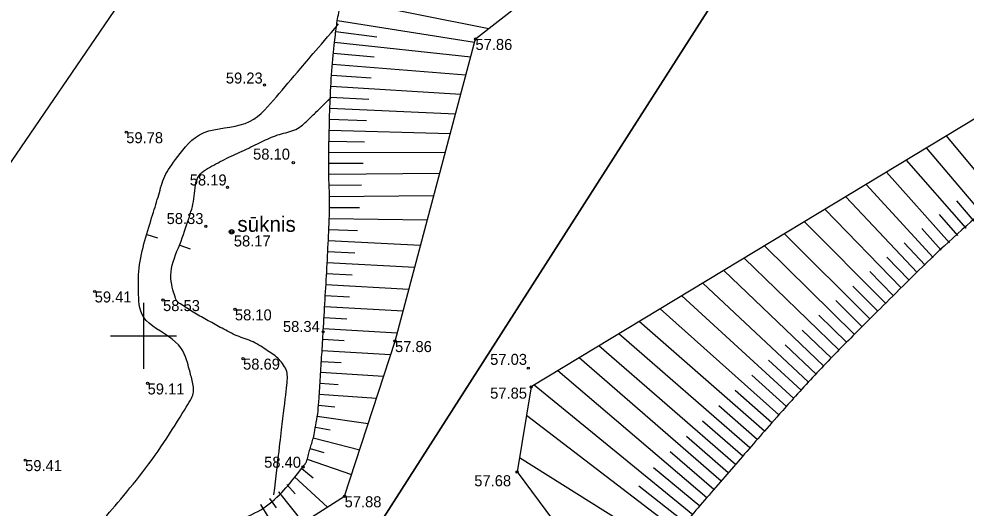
# Model space of a CAD drawing. Extents: x 616607 to 617499, y 408385 to 409695.
# Drawn here: x 616694.34 to 616737.38, y 408492.18 to 408514.38 of the extents above; entities that cross this region are included whole.
import ezdxf

# ---------------------------------------------------------------- set-up
doc = ezdxf.new("R2010")
doc.units = 0
for name, color, linetype in [('GEOD_ELEM_####_####_#', 7, 'Continuous'), ('HIDG_GRAV_####_####_#', 7, 'Continuous'), ('RAMI_UZMR_####_####_#', 7, 'Continuous'), ('RELJ_AATZ_####_TKST_#', 7, 'Continuous'), ('RELJ_ELEM_####_####_#', 7, 'Continuous'), ('RELJ_HORZ_PAMT_####_#', 7, 'Continuous'), ('RELJ_NOGA_####_####_#', 7, 'Continuous'), ('ROBZ_IERR_####_####_#', 7, 'Continuous'), ('ROBZ_UZMR_####_####_#', 7, 'Continuous'), ('UDTK_ELEM_####_####_#', 7, 'Continuous')]:
    doc.layers.add(name, color=color, linetype=linetype)

# ---------------------------------------------------------------- blocks, each defined once
blk = doc.blocks.new('PKT')
at = {"layer": 'RELJ_ELEM_####_####_#'}
blk.add_circle((0, 0), 0.05, dxfattribs=at)
blk = doc.blocks.new('UDSUKN')
at = {"layer": 'UDTK_ELEM_####_####_#'}
blk.add_circle((0, 0), 0.106, dxfattribs=at)
blk.add_text(' sūknis', height=0.7, dxfattribs=at).set_placement((0, 0))
blk = doc.blocks.new('KRUSTS')
at = {"layer": 'GEOD_ELEM_####_####_#'}
for p, q in [((0, 1.5), (0, 0)), ((-1.5, 0), (0, 0)), ((0, 0), (0, -1.5)), ((0, 0), (1.5, 0))]:
    blk.add_line(p, q, dxfattribs=at)

msp = doc.modelspace()

# ---------------------------------------------------------------- linework, layer by layer
at = {"layer": 'HIDG_GRAV_####_####_#'}
msp.add_lwpolyline([(616765.45, 408526.57), (616717.618, 408497.675), (616716.98, 408493.818), (616722.239, 408486.737), (616723.371, 408480.51), (616720.037, 408475.133), (616696.755, 408470.663), (616689.283, 408471.969), (616682.791, 408476.247), (616681.206, 408477.551), (616679.98, 408480.284), (616680.025, 408480.874), (616680.52, 408481.458), (616702.717, 408488.625), (616709.142, 408492.712), (616711.432, 408499.757), (616715.088, 408513.471), (616726.56, 408522.413), (616768.796, 408535.775)], dxfattribs=at)
at = {"layer": 'RAMI_UZMR_####_####_#'}
msp.add_lwpolyline([(617191.828, 409115.62), (617145.545, 408952.8), (617072.809, 408766.141), (616965.332, 408652.076), (616939.432, 408594.661), (616924.839, 408592.467), (616706.433, 408526.081), (616666.426, 408467.691)], dxfattribs=at)
at = {"layer": 'RELJ_HORZ_PAMT_####_#'}
for p, q in [((616700.159, 408504.591), (616700.635, 408504.438)), ((616701.653, 408504.116), (616702.121, 408503.939))]:
    msp.add_line(p, q, dxfattribs=at)
for points in [[(616696.187, 408489.283), (616697.051, 408490.308), (616697.915, 408491.333), (616698.779, 408492.358), (616699.992, 408493.796), (616701.077, 408495.342), (616702.062, 408496.949), (616702.342, 408497.407), (616702.195, 408498.072), (616702.062, 408498.557), (616701.728, 408499.776), (616699.817, 408500.621), (616699.782, 408501.889), (616699.75, 408503.051), (616700.055, 408504.338), (616700.432, 408505.53), (616700.706, 408506.398), (616700.914, 408507.26), (616701.474, 408508.013), (616702.562, 408509.474), (616704.808, 408509.403), (616705.94, 408510.727), (616706.917, 408511.87), (616707.893, 408513.013), (616708.87, 408514.156)], [(616705.931, 408492.781), (616706.128, 408494.455), (616706.325, 408496.129), (616706.523, 408497.803), (616706.59, 408498.372), (616706.179, 408498.964), (616705.677, 408499.298), (616704.989, 408499.757), (616704.251, 408499.964), (616703.564, 408500.342), (616702.947, 408500.681), (616702.34, 408501.017), (616701.736, 408501.406), (616701.613, 408501.486), (616701.488, 408501.594), (616701.447, 408501.728), (616701.099, 408502.866), (616701.684, 408504.165), (616702.068, 408505.34), (616702.338, 408506.163), (616702.335, 408507.276), (616703.097, 408507.689), (616703.887, 408508.117), (616704.687, 408508.469), (616705.485, 408508.853), (616706.157, 408509.175), (616706.968, 408509.296), (616707.502, 408509.815), (616707.84, 408510.144), (616708.178, 408510.473), (616708.516, 408510.803)]]:
    msp.add_open_spline(points, degree=3, dxfattribs=at)
at = {"layer": 'RELJ_NOGA_####_####_#'}
for p, q in [((616709.002, 408515.293), (616715.689, 408513.939)), ((616708.821, 408514.31), (616715.048, 408513.322)), ((616708.821, 408514.31), (616708.822, 408514.31)), ((616708.748, 408513.815), (616710.61, 408513.563)), ((616708.748, 408513.815), (616708.748, 408513.815)), ((616708.689, 408513.319), (616714.874, 408512.667)), ((616708.689, 408513.319), (616708.69, 408513.319)), ((616708.641, 408512.821), (616710.48, 408512.657)), ((616708.641, 408512.821), (616708.641, 408512.821)), ((616708.599, 408512.323), (616714.652, 408511.836)), ((616708.599, 408512.323), (616708.6, 408512.323)), ((616708.562, 408511.824), (616710.355, 408511.7)), ((616708.562, 408511.824), (616708.563, 408511.824)), ((616708.53, 408511.325), (616714.421, 408510.967)), ((616708.53, 408511.325), (616708.531, 408511.325)), ((616708.503, 408510.826), (616710.244, 408510.74)), ((616708.503, 408510.826), (616708.503, 408510.826)), ((616708.48, 408510.327), (616714.184, 408510.079)), ((616708.48, 408510.327), (616708.481, 408510.327)), ((616708.461, 408509.827), (616710.143, 408509.77)), ((616708.461, 408509.827), (616708.461, 408509.827)), ((616708.446, 408509.327), (616713.943, 408509.177)), ((616708.446, 408509.327), (616708.447, 408509.327)), ((616708.434, 408508.827), (616710.051, 408508.797)), ((616708.434, 408508.827), (616708.434, 408508.827)), ((616738.898, 408506.176), (616736.485, 408509.072)), ((616738.133, 408505.531), (616735.577, 408508.524)), ((616708.428, 408508.327), (616713.714, 408508.315)), ((616708.428, 408508.327), (616708.429, 408508.327)), ((616737.376, 408504.878), (616734.667, 408507.974)), ((616708.429, 408507.827), (616709.978, 408507.839)), ((616708.429, 408507.827), (616708.429, 408507.827)), ((616708.434, 408507.327), (616713.465, 408507.382)), ((616708.434, 408507.327), (616708.435, 408507.327)), ((616736.627, 408504.216), (616733.759, 408507.426)), ((616708.439, 408506.827), (616709.907, 408506.844)), ((616708.439, 408506.827), (616708.44, 408506.827)), ((616735.885, 408503.545), (616732.834, 408506.867)), ((616708.444, 408506.327), (616713.193, 408506.362)), ((616708.444, 408506.327), (616708.445, 408506.327)), ((616735.153, 408502.864), (616731.913, 408506.311)), ((616708.445, 408505.827), (616709.825, 408505.82)), ((616708.445, 408505.827), (616708.446, 408505.827)), ((616737.754, 408505.206), (616736.966, 408506.12)), ((616734.43, 408502.173), (616730.967, 408505.739)), ((616737, 408504.548), (616736.166, 408505.495)), ((616708.44, 408505.328), (616712.897, 408505.253)), ((616708.44, 408505.328), (616708.441, 408505.328)), ((616733.717, 408501.472), (616730.031, 408505.174)), ((616708.427, 408504.828), (616709.722, 408504.782)), ((616708.427, 408504.828), (616708.427, 408504.828)), ((616733.01, 408500.765), (616729.133, 408504.631)), ((616736.255, 408503.882), (616735.369, 408504.862)), ((616737, 408504.548), (616737, 408504.549)), ((616737.376, 408504.878), (616737.375, 408504.879)), ((616708.403, 408504.328), (616712.593, 408504.112)), ((616708.403, 408504.328), (616708.404, 408504.328)), ((616732.306, 408500.055), (616728.22, 408504.079)), ((616735.518, 408503.206), (616734.573, 408504.219)), ((616736.627, 408504.216), (616736.626, 408504.217)), ((616708.377, 408503.829), (616709.601, 408503.762)), ((616708.377, 408503.829), (616708.377, 408503.829)), ((616736.255, 408503.882), (616736.255, 408503.882)), ((616708.35, 408503.33), (616712.327, 408503.113)), ((616708.35, 408503.33), (616708.351, 408503.33)), ((616731.607, 408499.34), (616727.292, 408503.519)), ((616734.791, 408502.52), (616733.785, 408503.571)), ((616735.885, 408503.545), (616735.885, 408503.546)), ((616708.322, 408502.83), (616709.484, 408502.766)), ((616708.322, 408502.83), (616708.322, 408502.83)), ((616730.913, 408498.619), (616726.369, 408502.962)), ((616734.073, 408501.824), (616733.001, 408502.914)), ((616735.153, 408502.864), (616735.153, 408502.865)), ((616735.518, 408503.206), (616735.518, 408503.206)), ((616730.227, 408497.892), (616725.424, 408502.39)), ((616734.791, 408502.52), (616734.79, 408502.52)), ((616708.294, 408502.331), (616712.061, 408502.117)), ((616708.294, 408502.331), (616708.295, 408502.331)), ((616733.363, 408501.119), (616732.229, 408502.254)), ((616734.43, 408502.173), (616734.43, 408502.174)), ((616708.265, 408501.832), (616709.364, 408501.768)), ((616708.265, 408501.832), (616708.266, 408501.832)), ((616729.548, 408497.157), (616724.458, 408501.807)), ((616732.657, 408500.41), (616731.462, 408501.593)), ((616734.073, 408501.824), (616734.072, 408501.824)), ((616708.236, 408501.333), (616711.797, 408501.127)), ((616708.236, 408501.333), (616708.237, 408501.333)), ((616728.879, 408496.415), (616723.479, 408501.216)), ((616733.363, 408501.119), (616733.363, 408501.119)), ((616733.717, 408501.472), (616733.717, 408501.473)), ((616708.207, 408500.834), (616709.244, 408500.773)), ((616708.207, 408500.834), (616708.207, 408500.834)), ((616728.217, 408495.665), (616722.531, 408500.643)), ((616731.956, 408499.698), (616730.696, 408500.928)), ((616733.01, 408500.765), (616733.009, 408500.766)), ((616708.178, 408500.335), (616711.533, 408500.138)), ((616708.178, 408500.335), (616708.179, 408500.335)), ((616731.259, 408498.98), (616729.93, 408500.258)), ((616732.657, 408500.41), (616732.657, 408500.411)), ((616708.148, 408499.836), (616709.122, 408499.778)), ((616708.148, 408499.836), (616708.149, 408499.835)), ((616727.56, 408494.911), (616721.605, 408500.084)), ((616732.306, 408500.055), (616732.305, 408500.055)), ((616726.905, 408494.156), (616720.696, 408499.535)), ((616730.569, 408498.256), (616729.164, 408499.58)), ((616731.956, 408499.698), (616731.955, 408499.698)), ((616708.118, 408499.336), (616711.233, 408499.146)), ((616708.118, 408499.336), (616708.119, 408499.336)), ((616726.25, 408493.4), (616719.799, 408498.992)), ((616731.259, 408498.98), (616731.259, 408498.98)), ((616731.607, 408499.34), (616731.606, 408499.34)), ((616708.088, 408498.837), (616708.983, 408498.782)), ((616708.088, 408498.837), (616708.088, 408498.837)), ((616729.887, 408497.526), (616728.399, 408498.895)), ((616730.913, 408498.619), (616730.913, 408498.62)), ((616708.057, 408498.338), (616710.912, 408498.157)), ((616708.057, 408498.338), (616708.058, 408498.338)), ((616725.598, 408492.642), (616718.831, 408498.408)), ((616729.213, 408496.787), (616727.64, 408498.205)), ((616730.569, 408498.256), (616730.569, 408498.257)), ((616708.025, 408497.839), (616708.843, 408497.786)), ((616708.025, 408497.839), (616708.025, 408497.839)), ((616724.957, 408491.874), (616717.756, 408497.758)), ((616730.227, 408497.892), (616730.226, 408497.893)), ((616707.993, 408497.34), (616710.592, 408497.172)), ((616707.993, 408497.34), (616707.994, 408497.34)), ((616728.547, 408496.04), (616726.887, 408497.508)), ((616729.887, 408497.526), (616729.886, 408497.526)), ((616707.956, 408496.842), (616708.693, 408496.773)), ((616707.956, 408496.842), (616707.957, 408496.842)), ((616727.888, 408495.288), (616726.142, 408496.811)), ((616729.213, 408496.787), (616729.212, 408496.787)), ((616729.548, 408497.157), (616729.548, 408497.158)), ((616707.896, 408496.345), (616710.215, 408496.012)), ((616707.896, 408496.345), (616707.897, 408496.345)), ((616724.338, 408491.089), (616717.403, 408496.372)), ((616728.879, 408496.415), (616728.878, 408496.415)), ((616727.232, 408494.534), (616725.406, 408496.116)), ((616728.547, 408496.04), (616728.547, 408496.04)), ((616707.816, 408495.852), (616708.481, 408495.732)), ((616707.816, 408495.852), (616707.816, 408495.852)), ((616728.217, 408495.665), (616728.216, 408495.666)), ((616707.717, 408495.362), (616709.827, 408494.819)), ((616707.717, 408495.362), (616707.718, 408495.362)), ((616726.577, 408493.778), (616724.678, 408495.423)), ((616727.888, 408495.288), (616727.888, 408495.289)), ((616707.577, 408494.882), (616708.197, 408494.694)), ((616707.577, 408494.882), (616707.578, 408494.882)), ((616725.923, 408493.022), (616723.941, 408494.726)), ((616727.56, 408494.911), (616727.559, 408494.912)), ((616707.436, 408494.402), (616709.462, 408493.697)), ((616707.436, 408494.402), (616707.437, 408494.402)), ((616723.755, 408490.277), (616717.087, 408494.463)), ((616727.232, 408494.534), (616727.232, 408494.534)), ((616707.191, 408493.97), (616707.71, 408493.55)), ((616707.191, 408493.97), (616707.191, 408493.97)), ((616725.275, 408492.26), (616723.181, 408494.007)), ((616726.577, 408493.778), (616726.577, 408493.778)), ((616726.905, 408494.156), (616726.904, 408494.156)), ((616706.864, 408493.592), (616708.358, 408492.213)), ((616706.864, 408493.592), (616706.865, 408493.591)), ((616726.25, 408493.4), (616726.249, 408493.401)), ((616706.132, 408492.912), (616707.252, 408491.509)), ((616706.132, 408492.912), (616706.132, 408492.911)), ((616706.51, 408493.239), (616706.894, 408492.823)), ((616706.51, 408493.239), (616706.51, 408493.239)), ((616724.644, 408491.484), (616722.508, 408493.17)), ((616725.923, 408493.022), (616725.923, 408493.022)), ((616705.732, 408492.612), (616706.032, 408492.182)), ((616705.732, 408492.612), (616705.732, 408492.612)), ((616725.598, 408492.642), (616725.597, 408492.643)), ((616705.314, 408492.337), (616706.222, 408490.854)), ((616705.314, 408492.337), (616705.315, 408492.337)), ((616725.275, 408492.26), (616725.275, 408492.26))]:
    msp.add_line(p, q, dxfattribs=at)
msp.add_open_spline([(616975.731, 408606.41), (616971.71, 408604.144), (616967.689, 408601.878), (616963.668, 408599.612), (616962.341, 408598.864), (616961.192, 408597.791), (616960.311, 408596.511), (616959.39, 408595.173), (616958.675, 408593.776), (616958.002, 408592.329), (616957.302, 408590.825), (616956.736, 408589.272), (616956.015, 408587.778), (616955.313, 408586.324), (616954.582, 408584.882), (616953.626, 408583.572), (616952.496, 408582.025), (616951.261, 408580.593), (616950.022, 408579.143), (616948.785, 408577.695), (616947.537, 408576.278), (616946.22, 408574.895), (616945.626, 408574.271), (616944.957, 408573.742), (616944.225, 408573.278), (616943.451, 408572.788), (616942.648, 408572.387), (616941.804, 408572.051), (616941, 408571.73), (616940.2, 408571.414), (616939.368, 408571.187), (616938.69, 408571.002), (616938.005, 408570.852), (616937.329, 408570.663), (616918.615, 408565.441), (616899.903, 408560.204), (616881.253, 408554.75), (616874.57, 408552.796), (616867.991, 408550.484), (616861.269, 408548.669), (616855.483, 408547.106), (616849.688, 408545.577), (616843.9, 408544.023), (616838.111, 408542.469), (616832.323, 408540.916), (616826.537, 408539.352), (616816.497, 408536.637), (616806.51, 408533.737), (616796.541, 408530.774), (616791.553, 408529.292), (616786.584, 408527.751), (616781.609, 408526.226), (616776.622, 408524.697), (616771.656, 408523.11), (616766.688, 408521.515), (616762.607, 408520.204), (616758.677, 408518.521), (616754.775, 408516.687), (616750.921, 408514.875), (616747.341, 408512.653), (616743.915, 408510.109), (616740.341, 408507.454), (616736.942, 408504.677), (616733.801, 408501.555), (616732.131, 408499.895), (616730.49, 408498.223), (616728.926, 408496.468), (616728.114, 408495.556), (616727.318, 408494.632), (616726.518, 408493.709), (616725.695, 408492.76), (616724.91, 408491.864), (616724.122, 408490.803), (616723.665, 408490.187), (616723.18, 408489.459), (616723.332, 408488.764), (616723.537, 408487.829), (616723.949, 408486.896), (616724.213, 408485.954), (616724.975, 408483.236), (616725.742, 408480.486), (616726.381, 408477.738), (616726.631, 408476.667), (616726.554, 408475.507), (616726.221, 408474.429), (616726.043, 408473.855), (616725.77, 408473.346), (616725.415, 408472.86), (616725.226, 408472.602), (616725.032, 408472.37), (616724.813, 408472.14), (616724.582, 408471.898), (616724.347, 408471.683), (616724.071, 408471.48), (616723.783, 408471.268), (616723.475, 408471.091), (616723.13, 408471.039), (616722.812, 408470.991), (616722.494, 408470.986), (616722.176, 408470.982), (616721.543, 408470.975), (616720.901, 408471.154), (616720.278, 408471.02), (616716.569, 408470.219), (616712.93, 408469.339), (616709.261, 408468.478), (616707.424, 408468.047), (616705.589, 408467.613), (616703.751, 408467.182), (616701.927, 408466.754), (616700.076, 408466.424), (616698.236, 408466.115), (616695.42, 408465.64), (616692.315, 408465.565), (616689.691, 408467.073), (616684.319, 408470.158), (616679.892, 408473.486), (616675.008, 408476.777), (616674.831, 408476.896), (616674.652, 408477.012), (616674.483, 408477.14), (616674.175, 408477.376), (616674.46, 408477.978), (616674.696, 408478.288), (616675.427, 408479.251), (616676.165, 408480.2), (616676.939, 408481.135), (616677.893, 408482.289), (616678.812, 408483.429), (616679.848, 408484.532), (616681.078, 408485.839), (616682.698, 408486.726), (616684.412, 408487.237), (616686.183, 408487.764), (616687.958, 408488.143), (616689.768, 408488.401), (616691.642, 408488.668), (616693.528, 408488.826), (616695.398, 408489.116), (616696.323, 408489.26), (616697.239, 408489.444), (616698.155, 408489.647), (616699.054, 408489.848), (616699.912, 408490.166), (616700.785, 408490.476), (616703.122, 408491.305), (616705.613, 408491.942), (616707.248, 408494.043), (616707.429, 408494.275), (616707.474, 408494.537), (616707.552, 408494.798), (616707.628, 408495.051), (616707.711, 408495.3), (616707.761, 408495.559), (616707.86, 408496.068), (616707.943, 408496.577), (616707.977, 408497.092), (616708.044, 408498.12), (616708.108, 408499.147), (616708.168, 408500.175), (616708.254, 408501.63), (616708.34, 408503.085), (616708.414, 408504.54), (616708.488, 408505.998), (616708.403, 408507.461), (616708.436, 408508.92), (616708.468, 408510.38), (616708.539, 408511.837), (616708.686, 408513.293), (616708.76, 408514.026), (616708.887, 408514.749), (616709.039, 408515.47), (616709.116, 408515.834), (616709.208, 408516.193), (616709.297, 408516.554), (616709.387, 408516.92), (616709.487, 408517.278), (616709.619, 408517.635), (616710.681, 408520.51), (616712.959, 408522.898), (616715.736, 408524.335), (616718.688, 408525.863), (616721.668, 408526.887), (616724.792, 408527.643), (616730.078, 408528.922), (616735.359, 408530.207), (616740.655, 408531.436), (616749.901, 408533.581), (616759.244, 408535.317), (616768.413, 408537.779), (616798.7, 408545.91), (616828.618, 408555.288), (616858.746, 408563.964), (616877.646, 408569.406), (616896.581, 408574.731), (616915.501, 408580.089), (616916.131, 408580.267), (616916.803, 408580.127), (616917.44, 408580.402), (616917.832, 408580.571), (616918.181, 408580.992), (616918.136, 408581.394), (616918.071, 408581.969), (616918.005, 408582.544), (616917.94, 408583.119), (616917.87, 408583.733), (616917.799, 408584.347), (616917.73, 408584.96), (616917.674, 408585.454), (616917.97, 408585.948), (616918.384, 408586.3), (616918.906, 408586.742), (616919.445, 408586.959), (616920.02, 408587.218), (616920.568, 408587.465), (616921.093, 408587.698), (616921.676, 408587.899), (616922.792, 408588.284), (616923.918, 408588.529), (616925.044, 408588.565), (616925.938, 408588.594), (616926.854, 408588.454), (616927.734, 408588.123), (616928.677, 408587.768), (616929.526, 408587.359), (616930.432, 408586.999), (616931.324, 408586.645), (616932.223, 408586.313), (616933.127, 408585.998), (616933.97, 408585.704), (616934.935, 408585.706), (616935.807, 408585.922), (616937.564, 408586.355), (616939.443, 408587.201), (616940.422, 408588.724), (616944.438, 408594.972), (616948.27, 408601.228), (616952.11, 408607.531)], degree=3, dxfattribs=at)
at = {"layer": 'ROBZ_IERR_####_####_#'}
msp.add_lwpolyline([(616717.135, 408556.579), (616730.494, 408522.344), (616708.653, 408488.203), (616688.046, 408471.498), (616671.463, 408478.715), (616654.855, 408488.541)], dxfattribs=at)
at = {"layer": 'ROBZ_UZMR_####_####_#'}
msp.add_lwpolyline([(616704.998, 408460.626), (616695.309, 408466.84), (616688.046, 408471.498), (616708.653, 408488.203), (616730.494, 408522.344), (616805.459, 408543.657), (616889.795, 408568.012), (616940.576, 408582.801), (616958.517, 408604.593), (616968.565, 408608.405), (616974.837, 408605.827), (616993.227, 408598.268)], dxfattribs=at)

# ---------------------------------------------------------------- block references
at = {"layer": 'GEOD_ELEM_####_####_#'}
msp.add_blockref('KRUSTS', (616700, 408500), dxfattribs=at)
at = {"layer": 'RELJ_ELEM_####_####_#'}
for p in [(616715.088, 408513.471), (616705.503, 408511.378), (616699.22, 408509.239), (616706.811, 408507.855), (616703.823, 408506.739), (616702.837, 408504.964), (616704.01, 408504.716), (616697.788, 408502.009), (616700.893, 408501.617), (616704.158, 408501.196), (616708.168, 408500.175), (616711.432, 408499.757), (616704.53, 408498.96), (616717.485, 408498.527), (616700.191, 408497.834), (616717.618, 408497.675), (616694.626, 408494.353), (616707.248, 408494.043), (616716.98, 408493.818), (616709.142, 408492.712)]:
    msp.add_blockref('PKT', p, dxfattribs=at)
at = {"layer": 'UDTK_ELEM_####_####_#'}
msp.add_blockref('UDSUKN', (616704.01, 408504.716), dxfattribs=at)

# ---------------------------------------------------------------- texts
at = {"layer": 'RELJ_AATZ_####_TKST_#'}
for s, p in [('57.86', (616715.088, 408512.971)), ('59.23', (616703.746, 408511.448)), ('59.78', (616699.22, 408508.739)), ('58.10', (616704.985, 408507.993)), ('58.19', (616702.107, 408506.82)), ('58.33', (616701.056, 408505.069)), ('58.17', (616704.109, 408504.051)), ('59.41', (616697.788, 408501.509)), ('58.53', (616700.893, 408501.117)), ('58.10', (616704.158, 408500.696)), ('58.34', (616706.34, 408500.169)), ('57.86', (616711.432, 408499.257)), ('58.69', (616704.53, 408498.46)), ('57.03', (616715.756, 408498.676)), ('59.11', (616700.191, 408497.334)), ('57.85', (616715.756, 408497.144)), ('59.41', (616694.626, 408493.853)), ('58.40', (616705.487, 408494.007)), ('57.68', (616715.034, 408493.167)), ('57.88', (616709.142, 408492.212))]:
    msp.add_text(s, height=0.5, dxfattribs=at).set_placement(p)

doc.saveas('drawing.dxf')
